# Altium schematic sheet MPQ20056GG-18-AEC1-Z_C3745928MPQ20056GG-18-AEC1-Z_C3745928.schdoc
size 127 x 101 mm
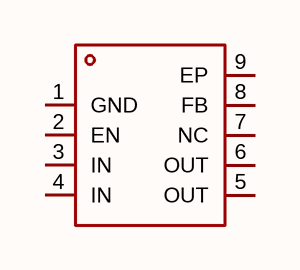
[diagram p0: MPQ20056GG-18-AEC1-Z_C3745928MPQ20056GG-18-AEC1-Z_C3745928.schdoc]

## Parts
U?  mpq20056gg-18-aec1-z_c3745928  [QFN-8_L2.0-W2.0-P0.50-BL-EP]  (value not drawn)

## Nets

Not connected (* = marked no-connect by the designer): U? 1(GND) 2(EN) 3(IN) 4(IN) 5(OUT) 6(OUT) 7(NC) 8(FB) 9(EP)

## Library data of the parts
U? = mpq20056gg-18-aec1-z_c3745928: 输出类型:固定;工作电压:5.5V;输出电压:1.8V;输出电流:250mA;电源纹波抑制比(PSRR):63dB@(1kHz);输出极性:正极;; Manufacturer: MPS(芯源); AddInBom: yes; ModelId: 86202c8e5c19411b879329bf817ae476; ModelTransform: 79.527,79.1337,0,90,0,0,0.005,0,0; Output Type: 固定; Voltage - Supply: 5.5V; Output Voltage: 1.8V; Output Current: 250mA; Voltage Dropout: 100mV@(250mA); standby current: 150uA; Noise: 20uVrms; Output Configuration: 正极; Number of Outputs: 1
